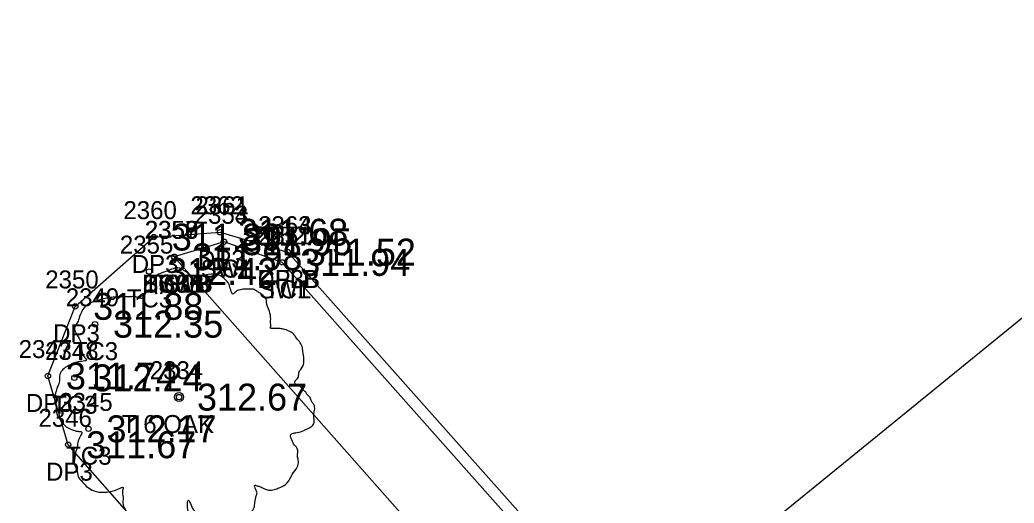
# Model space of a CAD drawing. Extents: x 1970076 to 1971136, y 803126 to 804215.
# Drawn here: x 1970356.3 to 1970411.6, y 803771.2 to 803798.1 of the extents above; entities that cross this region are included whole.
import ezdxf

# ---------------------------------------------------------------- set-up
doc = ezdxf.new("R2010")
doc.units = 0
for name, color, linetype in [('RD_EX_Conc', 7, 'Continuous'), ('RD_EX_Conc_txCode', 7, 'Continuous'), ('RD_EX_DR_Pipe', 7, 'Continuous'), ('RD_EX_Driveway', 7, 'Continuous'), ('RD_EX_Driveway_txCode', 7, 'Continuous'), ('RD_EX_TX_Conc_ELEV', 7, 'Continuous'), ('RD_EX_TX_Driveway_ELEV', 7, 'Continuous'), ('RD_EX_TX_VEG_ELEV', 7, 'Continuous'), ('RD_EX_VEG', 7, 'Continuous'), ('RD_EX_VEG_txCode', 7, 'Continuous'), ('RD_SMD_Locator', 7, 'Continuous')]:
    doc.layers.add(name, color=color, linetype=linetype)

msp = doc.modelspace()

# ---------------------------------------------------------------- linework, layer by layer
at = {"layer": 'RD_EX_Conc'}
msp.add_line((1970389.201, 803764.895), (1970371.192, 803785.158), dxfattribs=at)
for points in [[(1970403.64, 803748.467), (1970397.536, 803754.406), (1970390.789, 803761.917), (1970388.776, 803764.406), (1970370.879, 803784.584), (1970367.637, 803785.738), (1970364.866, 803784.899)], [(1970403.64, 803748.467), (1970400.496, 803744.573), (1970364.866, 803784.899)]]:
    msp.add_lwpolyline(points, dxfattribs=at)
at = {"layer": 'RD_EX_DR_Pipe'}
msp.add_line((1970391.537, 803764.762), (1970446.305, 803809.387), dxfattribs=at)
at = {"layer": 'RD_EX_Driveway'}
msp.add_lwpolyline([(1970401.094, 803743.669), (1970397.555, 803740.019), (1970391.952, 803738.507), (1970389.106, 803740.151), (1970358.957, 803774.425), (1970357.83, 803778.256), (1970359.349, 803782.137), (1970363.728, 803785.997), (1970367.42, 803786.267), (1970367.42, 803786.267), (1970371.192, 803785.158)], dxfattribs=at)
at = {"layer": 'RD_EX_VEG'}
for centre, radius in [((1970365.132, 803777.079), 0.25), ((1970365.12, 803777.06), 0.0001)]:
    msp.add_circle(centre, radius, dxfattribs=at)
for points in [[(1970365.264, 803784.246), (1970364.964, 803784.271), (1970364.639, 803784.171), (1970364.39, 803784.071), (1970364.165, 803783.996), (1970363.94, 803783.896), (1970363.64, 803783.721), (1970363.415, 803783.521), (1970363.29, 803783.272), (1970363.24, 803783.047), (1970363.19, 803782.772), (1970363.19, 803782.597), (1970363.065, 803782.572), (1970362.915, 803782.597), (1970362.665, 803782.672), (1970362.415, 803782.672), (1970362.165, 803782.672), (1970361.816, 803782.647), (1970361.466, 803782.647), (1970361.191, 803782.597), (1970360.866, 803782.547), (1970360.491, 803782.422), (1970360.141, 803782.297), (1970359.842, 803782.047), (1970359.592, 803781.572), (1970359.467, 803781.222), (1970359.317, 803780.973), (1970359.467, 803780.523), (1970359.642, 803780.173), (1970359.667, 803779.973), (1970359.742, 803779.548), (1970359.842, 803779.323), (1970359.966, 803779.123), (1970359.892, 803779.098), (1970359.517, 803779.048), (1970359.217, 803778.948), (1970358.792, 803778.724), (1970358.567, 803778.499), (1970358.467, 803778.174), (1970358.442, 803777.824), (1970358.342, 803777.624), (1970358.267, 803777.349), (1970358.242, 803777.274), (1970358.192, 803776.949), (1970358.292, 803776.499), (1970358.317, 803776.15), (1970358.442, 803775.925), (1970358.592, 803775.75), (1970358.767, 803775.5), (1970359.167, 803775.275), (1970359.492, 803775.175), (1970359.692, 803775.15), (1970359.517, 803774.65), (1970359.467, 803774.3), (1970359.342, 803773.901), (1970359.342, 803773.826), (1970359.292, 803773.351), (1970359.442, 803773.026), (1970359.517, 803772.651), (1970359.692, 803772.426), (1970359.966, 803772.126), (1970360.291, 803771.902), (1970360.791, 803771.777), (1970361.191, 803771.802), (1970361.766, 803771.976), (1970362.016, 803772.051), (1970361.991, 803771.877), (1970362.016, 803771.502), (1970362.016, 803771.077), (1970362.165, 803770.752), (1970362.265, 803770.477), (1970362.415, 803770.227), (1970362.74, 803770.002), (1970363.14, 803769.927), (1970363.565, 803769.777), (1970364.015, 803769.702), (1970364.514, 803769.677), (1970365.114, 803769.827), (1970365.389, 803769.952), (1970365.489, 803770.127), (1970365.689, 803770.502), (1970365.639, 803770.727), (1970365.664, 803771.327), (1970365.764, 803771.152), (1970365.939, 803770.802), (1970366.439, 803770.502), (1970366.838, 803770.327), (1970367.313, 803770.177), (1970367.613, 803770.102), (1970368.088, 803770.177), (1970368.463, 803770.252), (1970368.838, 803770.377), (1970369.137, 803770.652), (1970369.312, 803770.927), (1970369.362, 803771.202), (1970369.437, 803771.577), (1970369.487, 803771.752)], [(1970369.487, 803771.752), (1970369.412, 803771.927), (1970369.362, 803772.176), (1970369.437, 803772.151), (1970369.612, 803772.101), (1970369.887, 803771.976), (1970370.112, 803771.902), (1970370.437, 803771.927), (1970370.712, 803772.026), (1970371.162, 803772.301), (1970371.436, 803772.776), (1970371.711, 803773.176), (1970371.786, 803773.501), (1970371.736, 803773.726), (1970371.711, 803774.225), (1970371.511, 803774.475), (1970371.461, 803774.6), (1970371.361, 803775), (1970371.436, 803775.05), (1970371.711, 803775.1), (1970372.086, 803775.225), (1970372.361, 803775.35), (1970372.586, 803775.525), (1970372.661, 803775.75), (1970372.636, 803776.15), (1970372.686, 803776.549), (1970372.611, 803776.699), (1970372.511, 803776.849), (1970372.436, 803777.049), (1970372.286, 803777.199), (1970372.186, 803777.349), (1970372.086, 803777.449), (1970371.961, 803777.599), (1970371.786, 803777.724), (1970371.636, 803777.774), (1970371.586, 803777.924), (1970371.736, 803778.124), (1970371.786, 803778.224), (1970371.811, 803778.449), (1970372.036, 803778.798), (1970372.086, 803779.198), (1970372.036, 803779.623), (1970371.986, 803779.898), (1970371.836, 803780.173), (1970371.636, 803780.423), (1970371.511, 803780.598), (1970371.336, 803780.723), (1970371.012, 803780.848), (1970370.762, 803780.898), (1970370.412, 803780.898), (1970370.212, 803780.948), (1970370.237, 803780.998), (1970370.237, 803781.147), (1970370.237, 803781.422), (1970370.162, 803781.872), (1970370.012, 803782.372), (1970370.012, 803782.397), (1970369.912, 803782.647), (1970369.687, 803782.847), (1970369.512, 803782.947), (1970369.312, 803783.072), (1970369.062, 803783.097), (1970368.763, 803783.097), (1970368.488, 803783.047), (1970368.288, 803782.947), (1970368.113, 803782.822), (1970368.038, 803782.972), (1970367.938, 803783.272), (1970367.888, 803783.421), (1970367.738, 803783.596), (1970367.513, 803783.796), (1970367.063, 803783.921), (1970366.439, 803783.846), (1970366.139, 803783.646), (1970365.989, 803783.471), (1970365.939, 803783.596), (1970365.739, 803783.796), (1970365.639, 803783.971), (1970365.464, 803784.096), (1970365.314, 803784.196), (1970365.214, 803784.246)]]:
    msp.add_spline(points, degree=3, dxfattribs=at)
at = {"layer": 'RD_SMD_Locator'}
for centre in [(1970363.728, 803785.997), (1970367.42, 803786.267), (1970367.42, 803786.267), (1970367.637, 803785.738), (1970367.637, 803785.738), (1970364.866, 803784.899), (1970364.866, 803784.899), (1970364.866, 803784.899), (1970364.866, 803784.899), (1970371.192, 803785.158), (1970371.192, 803785.158), (1970370.879, 803784.584), (1970370.879, 803784.584), (1970363.467, 803784.076), (1970359.349, 803782.137), (1970360.455, 803781.141), (1970357.83, 803778.256), (1970359.305, 803778.153), (1970365.132, 803777.079), (1970360.09, 803775.312), (1970358.957, 803774.425)]:
    msp.add_circle(centre, 0.15, dxfattribs=at)

# ---------------------------------------------------------------- texts
at = {"layer": 'RD_EX_Conc_txCode'}
for s, p in [('2353', (1970366.007, 803786.738)), ('2354', (1970366.007, 803786.738)), ('2356', (1970363.212, 803785.899)), ('2357', (1970363.236, 803785.899)), ('2358', (1970363.236, 803785.899)), ('2359', (1970363.236, 803785.899)), ('2363', (1970369.538, 803786.158)), ('2355', (1970361.837, 803785.076)), ('2352', (1970369.249, 803785.584)), ('2351', (1970369.533, 803785.584)), ('SWL', (1970366.345, 803783.738)), ('TC1', (1970366.676, 803783.738)), ('SWLB', (1970363.102, 803782.899)), ('TC3B', (1970363.149, 803782.899)), ('BSWB', (1970363.078, 803782.899)), ('TC1B', (1970363.433, 803782.899)), ('CFLB', (1970369.514, 803783.158)), ('SWL', (1970369.588, 803782.584)), ('TC1', (1970369.918, 803782.584)), ('2349', (1970358.825, 803782.141)), ('TC3', (1970362.222, 803782.076)), ('2348', (1970357.675, 803779.153)), ('TC3', (1970359.211, 803779.141)), ('2345', (1970358.46, 803776.312)), ('TC3', (1970358.061, 803776.153)), ('TC3', (1970358.846, 803773.312))]:
    msp.add_text(s, height=1, dxfattribs=at).set_placement(p)
at = {"layer": 'RD_EX_Driveway_txCode'}
for s, p in [('2360', (1970362.035, 803786.997)), ('2362', (1970365.766, 803787.267)), ('2361', (1970366.05, 803787.267)), ('2364', (1970369.538, 803786.158)), ('DP3', (1970362.499, 803783.997)), ('DP3', (1970366.192, 803784.267)), ('DP3', (1970366.192, 803784.267)), ('2350', (1970357.68, 803783.137)), ('DP3B', (1970369.491, 803783.158)), ('DP3', (1970358.121, 803780.137)), ('2347', (1970356.2, 803779.256)), ('DP3', (1970356.601, 803776.256)), ('2346', (1970357.303, 803775.425)), ('DP3', (1970357.728, 803772.425))]:
    msp.add_text(s, height=1, dxfattribs=at).set_placement(p)
at = {"layer": 'RD_EX_TX_Conc_ELEV'}
for s, p in [('311.95', (1970368.637, 803784.988)), ('311.95', (1970368.637, 803784.988)), ('311.98', (1970365.866, 803784.149)), ('311.98', (1970365.866, 803784.149)), ('311.98', (1970365.866, 803784.149)), ('311.98', (1970365.866, 803784.149)), ('311.52', (1970372.192, 803784.408)), ('311.94', (1970371.879, 803783.834)), ('311.94', (1970371.879, 803783.834)), ('312.42', (1970364.467, 803783.326)), ('312.35', (1970361.455, 803780.391)), ('312.24', (1970360.305, 803777.403)), ('312.17', (1970361.09, 803774.562))]:
    msp.add_text(s, height=1.5, dxfattribs=at).set_placement(p)
at = {"layer": 'RD_EX_TX_Driveway_ELEV'}
for s, p in [('311.89', (1970364.728, 803785.247)), ('311.68', (1970368.42, 803785.517)), ('311.68', (1970368.42, 803785.517)), ('311.52', (1970372.192, 803784.408)), ('311.88', (1970360.349, 803781.387)), ('311.74', (1970358.83, 803777.506)), ('311.67', (1970359.957, 803773.675))]:
    msp.add_text(s, height=1.5, dxfattribs=at).set_placement(p)
at = {"layer": 'RD_EX_TX_VEG_ELEV'}
msp.add_text('312.67', height=1.5, dxfattribs=at).set_placement((1970366.132, 803776.329))
at = {"layer": 'RD_EX_VEG_txCode'}
for s, p in [('2334', (1970363.502, 803778.079)), ('T 6 OAK', (1970361.951, 803775.079))]:
    msp.add_text(s, height=1, dxfattribs=at).set_placement(p)

doc.saveas('drawing.dxf')
